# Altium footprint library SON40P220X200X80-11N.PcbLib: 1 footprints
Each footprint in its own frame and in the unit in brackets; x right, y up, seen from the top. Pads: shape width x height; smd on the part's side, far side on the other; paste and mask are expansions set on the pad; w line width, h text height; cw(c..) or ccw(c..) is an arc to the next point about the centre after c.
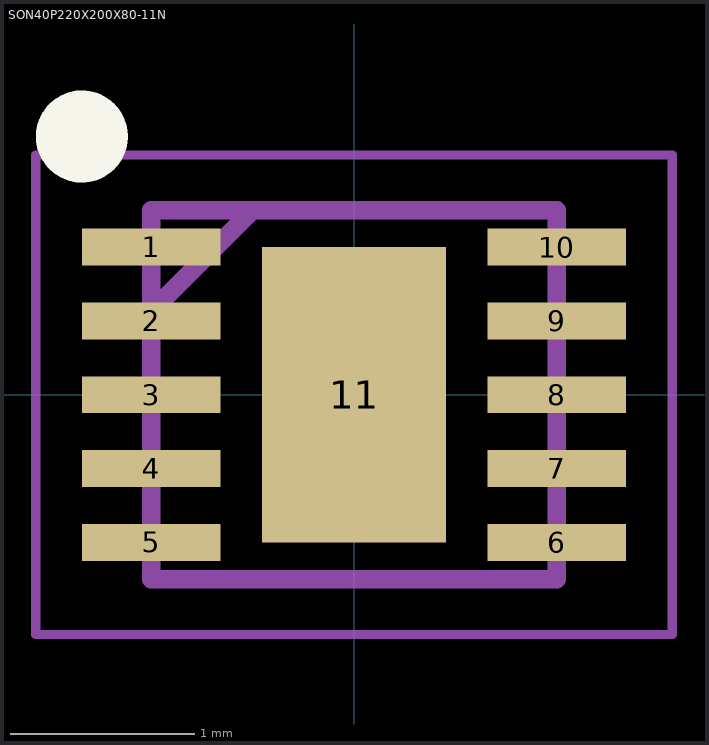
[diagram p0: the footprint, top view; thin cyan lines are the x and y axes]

## SON40P220X200X80-11N [mm]
pads (11):
  rect 0.75x0.2 smd: 1(-1.1,0.8) 2(-1.1,0.4) 3(-1.1,0) 4(-1.1,-0.4) 5(-1.1,-0.8) 6(1.1,-0.8) 7(1.1,-0.4) 8(1.1,0) 9(1.1,0.4) 10(1.1,0.8)
  rect 1x1.6 smd: 11(0,0)
Top Overlay:
  circle w0.25: c-1.475,1.4 r0.125
Mechanical 15:
  lines w0.1: -1.1,0.45 -0.55,1 ; -1.1,-1 1.1,-1 1.1,1 -1.1,1 -1.1,-1
Mechanical 20:
  lines w0.05: -1.725,-1.3 1.725,-1.3 1.725,1.3 -1.725,1.3 -1.725,-1.3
